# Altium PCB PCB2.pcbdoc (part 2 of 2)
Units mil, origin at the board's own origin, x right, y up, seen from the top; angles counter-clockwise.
Board outline 4625.8 x 3614.6 mil, 4 copper layers (Top Layer, Inner1, Inner2, Bottom Layer); 121 components, 127 nets, 523 pads, 246 vias.
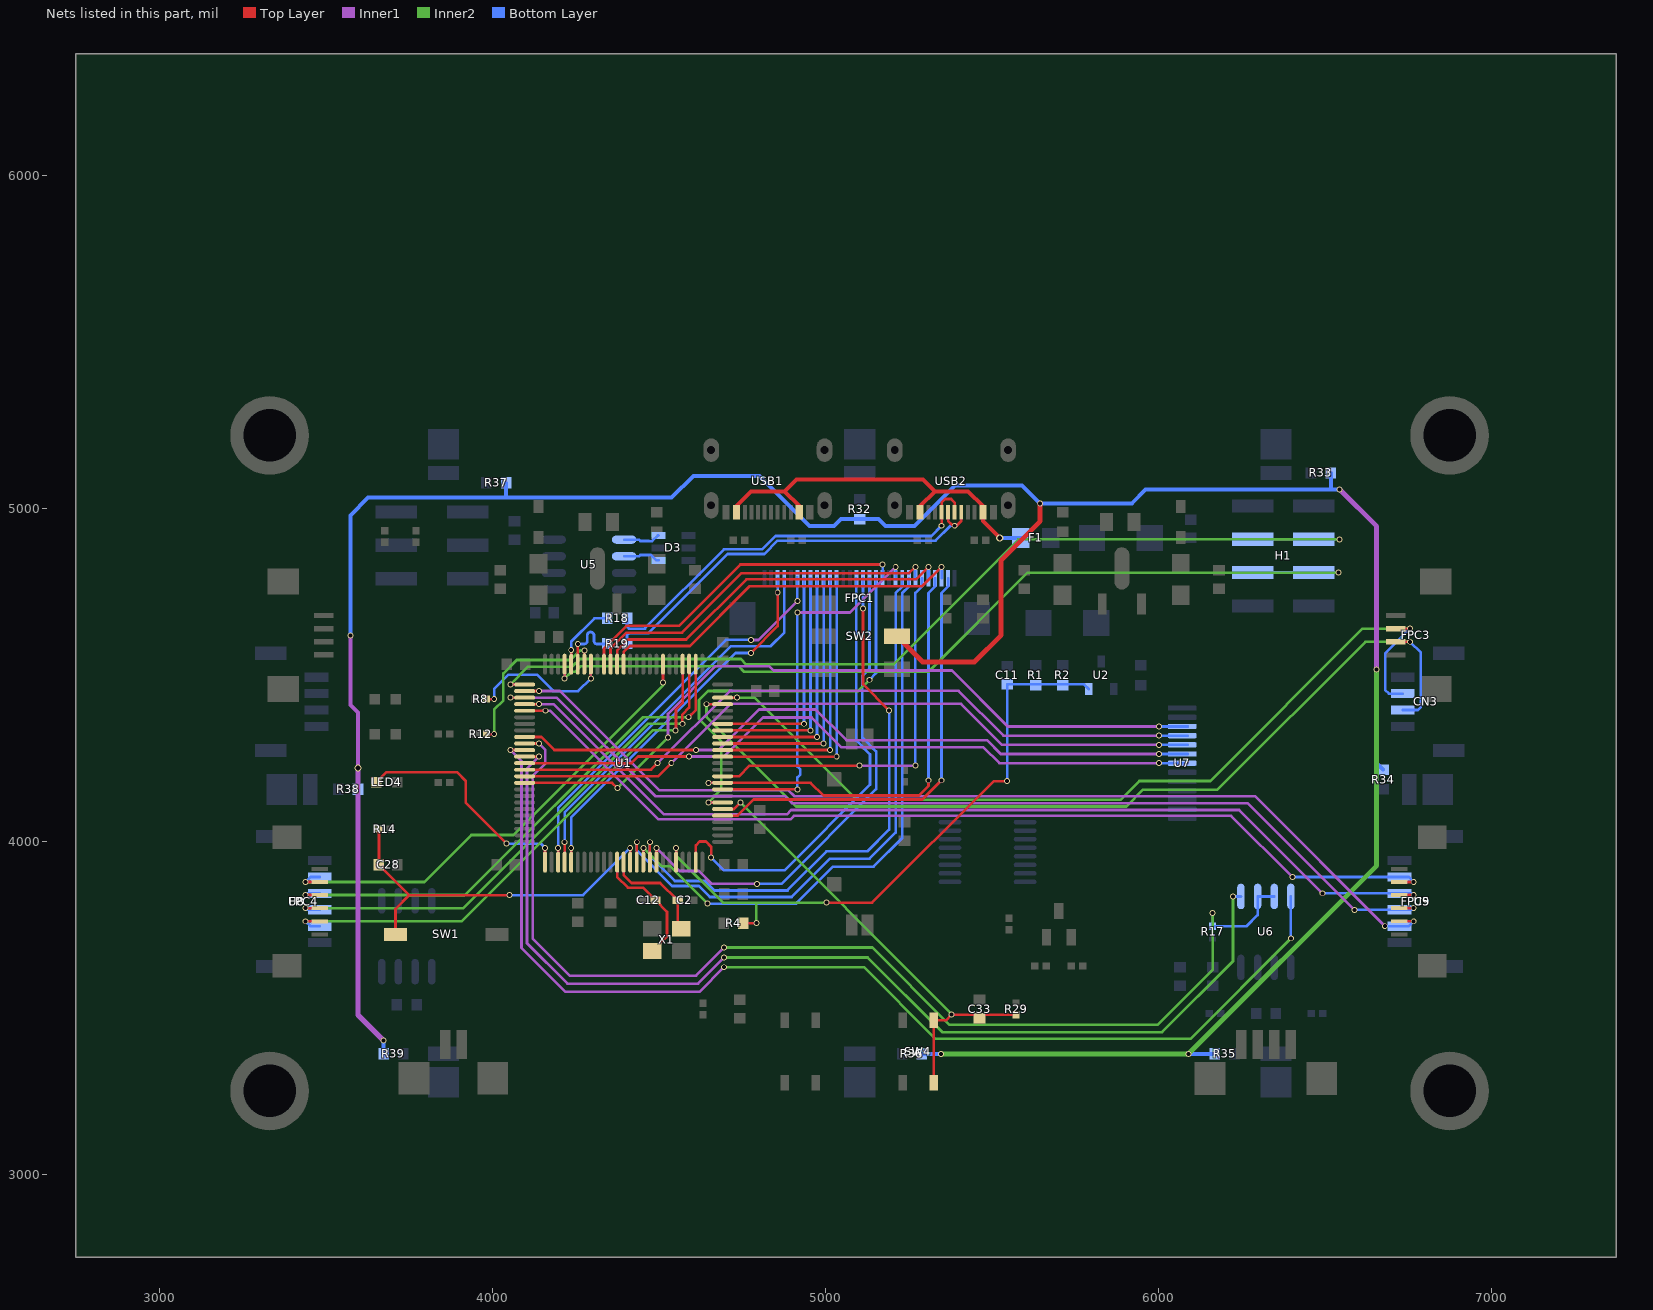
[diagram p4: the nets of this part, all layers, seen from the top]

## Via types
v1: diameter 17.7, hole 12, Top Layer to Bottom Layer, 177 vias
v2: diameter 22, hole 14, Top Layer to Bottom Layer, 62 vias
v3: diameter 17.7, hole 12.01, Top Layer to Bottom Layer, 6 vias
v4: diameter 24, hole 15, Top Layer to Bottom Layer, 1 vias

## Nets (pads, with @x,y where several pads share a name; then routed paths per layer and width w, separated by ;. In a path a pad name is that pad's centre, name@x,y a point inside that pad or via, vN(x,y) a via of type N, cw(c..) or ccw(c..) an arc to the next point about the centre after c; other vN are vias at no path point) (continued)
M0_SPI2_CS: FPC4.5 U1.57 U8.5 | length 1472.9
  Top Layer w8: v1(3440.17,3877.65) FPC4.5@3483.1,3877.6 ; v1(4513.3,4476.86) U1.57@4513.35,4531.59
  Inner2 w8: v1(3440.17,3877.65) 3796.75,3877.65 3937.7,4018.6 4064,4018.6 4513.3,4467.9 v1(4513.3,4476.86)
  Bottom Layer w8: v1(3440.17,3877.65) 3454.94,3892.42 U8.5@3482.8,3892.42
M0_SPI2_MISO: FPC4.3 U1.53 U8.3 | length 1635.9
  Top Layer w8: v1(3440.17,3798.91) FPC4.3@3483.1,3798.9 ; v1(4571.42,4352.61) 4571.27,4352.76 4571.27,4380.11 4592.09,4400.92 U1.53@4592.09,4531.59
  Inner2 w8: v1(3440.17,3798.91) 3913.91,3798.91 4467.61,4352.61 v1(4571.42,4352.61)
  Bottom Layer w8: v1(3440.17,3798.91) 3445.09,3793.99 U8.3@3482.8,3793.99
M0_SPI2_MOSI: FPC4.2 U1.54 U8.2 | length 1647.4
  Top Layer w8: v1(3440.17,3759.54) FPC4.2@3483.1,3759.5 ; v1(4550.75,4332.93) 4552.57,4334.74 4552.57,4394.87 4572.41,4414.71 U1.54@4572.41,4531.59
  Inner2 w8: v1(3440.17,3759.54) 3908.84,3759.54 4482.23,4332.93 v1(4550.75,4332.93)
  Bottom Layer w8: v1(3440.17,3759.54) 3454.93,3744.78 U8.2@3482.8,3744.78
M0_SPI2_SCK: FPC4.4 U1.52 U8.4 | length 1627
  Top Layer w8: v1(3440.17,3838.28) FPC4.4@3483.1,3838.3 ; v1(4590.12,4372.3) 4611.78,4393.95 U1.52@4611.78,4531.59
  Inner2 w8: v1(3440.17,3838.28) 3918.78,3838.28 4452.8,4372.3 v1(4590.12,4372.3)
  Bottom Layer w8: v1(3440.17,3838.28) 3445.1,3843.21 U8.4@3482.8,3843.21
M0_TIM1_CH1: FPC1.20 U1.40 | length 839
  Top Layer w8: U1.40@4692.48,4273.72 v1(5015.31,4273.72)
  Bottom Layer w8: v1(5015.31,4273.72) FPC1.20@5015.31,4789.85
M0_TIM1_CH1N: FPC1.19 U1.39 | length 878.3
  Top Layer w8: U1.39@4692.48,4254.04 v1(5035,4254.04)
  Bottom Layer w8: v1(5035,4254.04) FPC1.19@5035.01,4789.85
M0_TIM1_CH2: FPC1.22 U1.42 | length 760.2
  Top Layer w8: U1.42@4692.48,4313.09 v1(4975.94,4313.09)
  Bottom Layer w8: v1(4975.94,4313.09) FPC1.22@4975.94,4789.85
M0_TIM1_CH2N: FPC1.21 U1.41 | length 799.5
  Top Layer w8: U1.41@4692.48,4293.41 4995.48,4293.41 v1(4995.63,4293.55)
  Bottom Layer w8: v1(4995.63,4293.55) FPC1.21@4995.64,4789.85
M0_TIM1_CH3: FPC1.24 U1.44 | length 681.4
  Top Layer w8: U1.44@4692.48,4352.46 4936.42,4352.46 v1(4936.57,4352.61)
  Bottom Layer w8: v1(4936.57,4352.61) FPC1.24@4936.57,4789.85
M0_TIM1_CH3N: FPC1.23 U1.43 | length 720.8
  Top Layer w8: U1.43@4692.48,4332.78 4956.12,4332.78 v1(4956.27,4332.93)
  Bottom Layer w8: v1(4956.27,4332.93) FPC1.23@4956.27,4789.85
M1_ADC: FPC1.10 U1.34 | length 1148.7
  Top Layer w8: U1.34@4692.48,4155.61 v1(4916.9,4155.61)
  Inner1 w8: v1(4916.9,4686.6) 5074.77,4686.6 v1(5212.18,4824)
  Bottom Layer w8: v1(4916.9,4155.61) 4916.9,4191.59 4925.59,4200.29 4925.59,4215.9 4916.9,4224.6 v1(4916.9,4686.6) ; FPC1.10@5212.17,4790.13 v1(5212.18,4824)
M1_ADC_A: FPC1.9 U1.15 | length 1772.7
  Top Layer w8: U1.15@4434.61,3937.11 v1(4434.61,3997.05)
  Bottom Layer w8: v1(4434.61,3997.05) 4434.61,3971.89 4540.9,3865.6 4620.9,3865.6 4653.9,3832.6 4899.9,3832.6 5014.9,3947.6 5133.8,3947.6 5212,4025.8 5212,4745.31 5231.9,4765.21 FPC1.9@5231.9,4790.08
M1_ADC_C: FPC1.8 U1.16 | length 1760
  Top Layer w8: U1.16@4454.3,3937.11 v1(4454.3,3980.05)
  Inner2 w8: v1(4454.3,3980.05) 4509.75,3924.6 4535.24,3924.6 v1(4647.12,3812.72)
  Bottom Layer w8: v1(4647.12,3812.72) 4913.02,3812.72 5023.9,3923.6 5145.8,3923.6 5231.85,4009.66 5231.85,4745.49 5251.54,4765.17 FPC1.8@5251.54,4790.13
M1_BK_BUTTON: C33.2 R29.2 SW4.1 SW4.2 U1.31 | length 1410.6
  Top Layer w8: U1.31@4692.48,4096.55 4726.13,4096.55 v1(4745.82,4116.24) ; SW4.1@5326.89,3274.5 SW4.2@5326.9,3462.31 5363.41,3462.31 v1(5380.2,3479.1) R29.2@5573.9,3479.06 ; C33.2@5463.9,3468.54 C33.2@5469.16,3473.8
  Inner2 w8: v1(4745.82,4116.24) 5380.2,3481.86 v1(5380.2,3479.1)
M1_BK_OUT: FPC1.25 U1.3 | length 1222.3
  Top Layer w8: U1.3@4198.39,3921.16 v1(4198.39,3980.05)
  Inner1 w8: v1(4777.17,4604.45) 4800.39,4604.45 v1(4916.9,4720.95)
  Bottom Layer w8: v1(4198.39,3980.05) 4198.39,4100.29 4702.7,4604.6 4773.6,4604.6 v1@4773.75,4604.45 ; v1(4916.9,4720.95) FPC1.25@4916.9,4791.86
M1_I2C2_SCL: CN3.3 FPC3.2 U1.47 | length 2825.2
  Top Layer w8: v1(4644.14,4411.37) 4655.87,4411.37 4656.01,4411.52 U1.47@4692.48,4411.52 ; FPC3.2@6713.4,4598.9 v1(6756.34,4598.9)
  Inner2 w8: v1(4644.14,4411.37) 4644.14,4373.18 4912.92,4104.4 5904.7,4104.4 5954.9,4154.6 6177.9,4154.6 6622.2,4598.9 v1(6756.34,4598.9)
  Bottom Layer w8: CN3.3@6735,4393.99 6780.29,4393.99 6788.9,4402.6 6788.9,4566.34 v1(6756.34,4598.9)
M1_I2C2_SDA: CN3.2 FPC3.3 U1.48 | length 2718.6
  Top Layer w8: U1.48@4692.48,4431.2 v1(4735.42,4431.2) ; FPC3.3@6713.4,4638.2 v1(6756.34,4638.2)
  Inner2 w8: v1(4735.42,4431.2) 4787.5,4431.2 5093.9,4124.8 5888.1,4124.8 5943.9,4180.6 6156.9,4180.6 6614.5,4638.2 v1(6756.34,4638.2)
  Bottom Layer w8: CN3.2@6735,4443.21 6693.29,4443.21 6681.9,4454.6 6681.9,4563.76 v1(6756.34,4638.2)
M1_SPI3_CS: FPC5.5 U1.77 U9.5 | length 3011.2
  Top Layer w8: U1.77@4098,4450.89 v1(4140.94,4450.89) ; FPC5.5@6724.7,3759.6 v1(6767.63,3759.55)
  Inner1 w8: v1(4140.94,4450.89) 4203.93,4450.89 4502.22,4152.6 4890,4152.6 4907.5,4135.1 6290.4,4135.1 v1(6680.72,3744.78)
  Bottom Layer w8: v1(6680.72,3744.78) U9.5@6725,3744.78 6752.86,3744.78 v1(6767.63,3759.55)
M1_SPI3_MISO: FPC5.3 U1.79 U9.3 | length 2964.3
  Top Layer w8: U1.79@4098,4411.52 v1(4140.94,4411.52) ; FPC5.3@6724.7,3838.3 v1(6767.63,3838.29)
  Inner1 w8: v1(4140.94,4411.52) 4185.23,4411.52 4515.96,4080.79 4885.09,4080.79 4898,4093.7 6243.65,4093.7 v1(6493.75,3843.6)
  Bottom Layer w8: v1@6493.35,3843.21 v1(6493.75,3843.6) 6727.6,3843.6 U9.3@6728,3843.21 ; U9.3@6725,3843.21 U9.3@6728,3843.21 ; v1(6767.63,3838.29) 6762.71,3843.21 U9.3@6728,3843.21
M1_SPI3_MOSI: FPC5.2 U1.80 U9.2 | length 2934.3
  Top Layer w8: U1.80@4098,4391.83 v1(4161.06,4391.83) ; FPC5.2@6724.7,3877.7 v1(6767.63,3877.66)
  Inner1 w8: v1(4161.06,4391.83) 4173.42,4391.83 4499.46,4065.79 4896.19,4065.79 4906.7,4076.3 6219.64,4076.3 v1(6403.35,3892.59)
  Bottom Layer w8: v1(6403.35,3892.59) 6403.52,3892.42 U9.2@6725,3892.42 6752.87,3892.42 v1(6767.63,3877.66)
M1_SPI3_SCK: FPC5.4 U1.78 U9.4 | length 3064.4
  Top Layer w8: v1(4055.05,4431.2) U1.78@4098,4431.2 ; FPC5.4@6724.7,3798.9 v1(6767.63,3798.92)
  Inner1 w8: v1(4055.05,4431.2) 4194.09,4431.2 4490.07,4135.22 4879.38,4135.22 4900.1,4114.5 6268.8,4114.5 v1(6589.3,3793.99)
  Bottom Layer w8: v1(6589.3,3793.99) U9.4@6725,3793.99 6762.7,3793.99 v1(6767.63,3798.92)
M1_TIM8_CH1: FPC1.3 U1.63 | length 1146.8
  Top Layer w8: U1.63@4395.24,4515.64 4395.24,4567.6 4413.94,4586.3 4594.2,4586.3 4773.5,4765.6 5291.56,4765.6 v1(5349.96,4824)
  Bottom Layer w8: FPC1.3@5349.96,4790.13 v1(5349.96,4824)
M1_TIM8_CH1N: FPC1.2 U1.30 | length 1316.7
  Top Layer w8: U1.30@4692.48,4076.87 4737.17,4076.87 4785.34,4125.04 5291.9,4125.04 v1(5349.9,4183.04)
  Bottom Layer w8: v1(5349.9,4183.04) 5349.9,4745.42 5369.65,4765.17 FPC1.2@5369.65,4790.13
M1_TIM8_CH2: FPC1.5 U1.64 | length 1130.2
  Top Layer w8: U1.64@4375.56,4515.64 4375.56,4572.92 4408.54,4605.9 4583,4605.9 4763.7,4786.6 5273.19,4786.6 v1(5310.59,4824)
  Bottom Layer w8: FPC1.5@5310.59,4790.13 v1(5310.59,4824)
M1_TIM8_CH2N: FPC1.4 U1.35 | length 1321.3
  Top Layer w8: v1(4649.53,4175.29) U1.35@4692.48,4175.29 4956.91,4175.29 4995.16,4137.04 5281.99,4137.04 5310.7,4165.75 v1@5310.7,4182.94
  Bottom Layer w8: v1(5310.7,4183.04) 5310.7,4745.59 5330.28,4765.17 FPC1.4@5330.28,4790.13
M1_TIM8_CH3: FPC1.7 U1.65 | length 1113.7
  Top Layer w8: U1.65@4355.87,4515.64 4355.87,4578.23 4403.84,4626.2 4570.6,4626.2 4749.55,4805.15 5252.37,4805.15 v1(5271.22,4824)
  Bottom Layer w8: FPC1.7@5271.22,4790.13 v1(5271.22,4824)
M1_TIM8_CH3N: FPC1.6 U1.36 | length 1163.3
  Top Layer w8: U1.36@4692.48,4194.98 4741.17,4194.98 4773.14,4226.94 v1(5103.9,4226.94)
  Inner1 w8: v1(5103.9,4226.94) v1(5271.23,4226.9)
  Bottom Layer w8: v1(5271.23,4226.9) 5271.23,4745.49 5290.91,4765.17 FPC1.6@5290.91,4790.13
MOTOR_EN1: FPC1.27 U1.4 | length 1196
  Top Layer w8: U1.4@4218.07,3937.11 v1(4218.07,3997.05)
  Bottom Layer w8: v1(4218.07,3997.05) 4218.07,4086.37 4717.3,4585.6 4836.9,4585.6 4877.52,4626.23 FPC1.27@4877.52,4789.85
MOTOR_EN2: FPC1.28 U1.5 | length 1152.2
  Top Layer w8: U1.5@4237.76,3921.16 v1(4237.76,3980.05) ; v1(4777.17,4565.29) 4857.84,4645.95 v1(4857.84,4746.51)
  Bottom Layer w8: v1(4237.76,3980.05) 4237.76,4071.46 4731.59,4565.29 v1(4777.17,4565.29) ; v1(4857.84,4746.51) FPC1.28@4857.84,4789.85
NRST: C28.2 R14.1 SW1.2 U1.14 | length 1136.2
  Top Layer w8: R14.1@3660.3,4036.44 C28.2@3660.34,3929.05 3751.31,3838.08 ; SW1.2@3710.34,3720.2 3710.34,3797.05 3751.38,3838.08 v1(4052.32,3838.08) ; U1.14@4414.93,3937.11 v1(4414.93,3980.05)
  Bottom Layer w8: v1(4052.32,3838.08) 4272.96,3838.08 v1(4414.93,3980.05)
OSC_IN: C12.1 U1.12 X1.1 | length 357.8
  Top Layer w8: U1.12@4375.56,3921.16 4375.56,3892.94 4407.96,3860.54 4453.01,3860.54 C12.1@4490.76,3822.79 4525.5,3788.05 4525.5,3714.08 X1.1@4481.49,3670.07
OSC_OUT: C2.1 U1.13 X1.3 | length 306.8
  Top Layer w8: U1.13@4395.24,3921.16 4395.24,3898.26 4418.96,3874.54 4504.69,3874.54 4556.44,3822.79 C2.1@4557.84,3822.79 4557.84,3747.27 X1.3@4568.11,3737
OTG_D+: R18.1 USB2.6 USB2.8 | length 1248.7
  Top Layer w8: USB2.8@5349.97,4987.3 5349.97,5016.81 5360.8,5027.65 5378.52,5027.65 5389.34,5016.83 USB2.6@5389.34,4987.3 ; v1(5350,4947.3) USB2.8@5349.97,4987.3
  Bottom Layer w8: R18.1@4405.4,4669.1 4405.4,4644.01 4411.06,4638.35 4457.81,4638.35 ; 4459.15,4638.35 4457.81,4638.35 ; v1(5350,4947.3) 5319.28,4916.58 4851.1,4916.58 4811.11,4876.6 4696.06,4876.6 4457.81,4638.35
OTG_D-: R19.1 USB2.5 USB2.7 | length 1248.9
  Top Layer w8: USB2.7@5369.65,4987.3 5369.65,4961.75 5384.1,4947.3 v1(5389.34,4947.3) 5394.6,4947.3 5409.02,4961.72 USB2.5@5409.02,4987.3
  Bottom Layer w8: R19.1@4405.4,4593.6 4405.4,4618.69 4411.06,4624.35 4468.65,4624.35 ; 4469.99,4624.35 4468.65,4624.35 ; v1(5389.34,4947.3) 5376.66,4947.3 5331.94,4902.58 4857.88,4902.58 4817.9,4862.6 4706.9,4862.6 4468.65,4624.35
PA1: FPC1.16 U1.24 | length 1376.7
  Top Layer w8: U1.24@4611.78,3937.11 4611.78,3987.03 4623.65,3998.9 4642.4,3998.9 4657.9,3983.4 v1(4657.9,3950.7)
  Bottom Layer w8: v1(4657.9,3950.7) 4696,3912.6 4878,3912.6 5135.1,4169.7 5135.1,4260.7 5094.06,4301.74 FPC1.16@5094.06,4789.85
PA7: FPC1.13 U1.32 | length 1244.1
  Top Layer w8: v1(4649.53,4116.24) U1.32@4692.48,4116.24
  Inner2 w8: v1(4649.53,4116.24) 4687.9,4154.6 4687.9,4300.6 4621.7,4366.8 4621.7,4423.4 4649.2,4450.9 5099.58,4450.9 v1(5133.38,4484.7)
  Bottom Layer w8: v1(5133.38,4484.7) 5153.11,4504.43 FPC1.13@5153.11,4790.13
PA9: R8.2 U1.68 | length 440.6
  Top Layer w8: R8.2@3983.28,4426.6 v1(4006.56,4426.6) ; v1(4296.81,4488.64) U1.68@4296.81,4531.59
  Bottom Layer w8: v1(4006.56,4426.6) 4006.56,4456.54 4049.96,4499.94 4135.09,4499.94 4184.44,4450.6 4258.76,4450.6 v1(4296.81,4488.64)
PA10: R12.2 U1.69 | length 529.3
  Top Layer w8: R12.2@3983.28,4321.71 v1(4006.56,4321.71) ; U1.69@4277.13,4531.59 v1(4277.13,4572.53)
  Inner2 w8: v1(4006.56,4321.71) 4006.56,4395.26 4033.9,4422.6 4033.9,4503.65 4074.2,4543.96 4236.06,4543.96 4264.63,4572.53 v1(4277.13,4572.53)
PA11: R19.2 U1.70 | length 204.7
  Top Layer w8: U1.70@4257.44,4531.59 v1(4257.44,4592)
  Bottom Layer w8: v1(4257.44,4592) 4276.17,4592 ccw(c4276.17,4602) 4286.17,4602 4286.17,4618.05 cw(c4296.17,4618.05) 4306.17,4618.05 4306.17,4602 ccw(c4316.17,4602) 4316.17,4592 4344.47,4592 R19.2@4346.08,4593.6
PA12: R18.2 U1.71 | length 204.8
  Top Layer w8: U1.71@4237.76,4531.59 v1(4237.76,4574.53)
  Bottom Layer w8: v1(4237.76,4574.53) 4237.76,4598.97 4307.88,4669.1 R18.2@4346.08,4669.1
PA13: H1.5 H1.6 U1.72 | length 2758.7
  Top Layer w8: v1(4218.07,4488.64) U1.72@4218.07,4531.59
  Inner2 w8: v1(4218.07,4488.64) 4238.32,4508.9 4250.85,4508.9 4267.79,4525.84 4740.33,4525.84 4757.28,4508.9 5310,4508.9 5607.7,4806.6 v1(6541.31,4806.6)
  Bottom Layer w8: H1.5@6284.37,4806.8 H1.6@6467.83,4806.8 ; H1.6@6478.01,4806.6 v1(6541.31,4806.6)
PA14: H1.3 H1.4 U1.76 | length 2973.9
  Top Layer w8: v1(4055.06,4470.57) U1.76@4098,4470.57
  Inner2 w8: v1(4055.06,4470.57) 4108.43,4523.94 4240.84,4523.94 4264.04,4547.14 4747.36,4547.14 4763.3,4531.2 5205.5,4531.2 5580.9,4906.6 v1(6545.4,4906.6)
  Bottom Layer w8: H1.3@6284.37,4906.8 H1.4@6467.83,4906.8 ; H1.4@6482.1,4906.6 v1(6545.4,4906.6)
PB3: U1.89 U7.4 | length 2145.1
  Top Layer w8: U1.89@4098,4214.67 4477.11,4214.67 v1(4496.94,4234.5)
  Inner1 w8: v1(4496.94,4234.5) 4714.05,4451.6 5401.26,4451.6 5535.83,4317.03 v1(6002.65,4317.03)
  Bottom Layer w8: v1(6002.65,4317.03) U7.4@6089.18,4317.03
PB4: U1.90 U7.5 | length 2132.1
  Top Layer w8: U1.90@4098,4194.98 4498.76,4194.98 v1(4538.28,4234.5)
  Inner1 w8: v1(4538.28,4234.5) 4716.13,4412.35 5408.03,4412.35 5530.91,4289.47 v1(6002.65,4289.47)
  Bottom Layer w8: v1(6002.65,4289.47) U7.5@6089.18,4289.47
PB5: U1.91 U7.3 | length 2266.6
  Top Layer w8: U1.91@4098,4175.29 4360.84,4175.29 v1(4376.78,4159.34)
  Inner1 w8: v1(4528.44,4311.27) 4528.44,4382.57 4671.71,4525.85 4832.04,4525.85 4845.39,4512.5 5380.71,4512.5 5548.63,4344.58 v1(6002.65,4344.58)
  Inner2 w8: v1(4376.78,4159.34) 4528.44,4311 v1(4528.44,4311.27)
  Bottom Layer w8: v1(6002.65,4344.58) U7.3@6089.18,4344.58
PC2: FPC1.15 U1.17 | length 1725.9
  Top Layer w8: U1.17@4473.98,3937.11 v1(4473.98,3997.05) ; v1(5113.73,4698.26) 5113.73,4471.77 v1(5192.5,4393)
  Bottom Layer w8: v1(4473.98,3997.05) 4473.98,3955.52 4548.9,3880.6 4639.7,3880.6 4668.35,3851.95 4887.85,3851.95 ; 4887.85,3852.95 5004.5,3969.6 5126.7,3969.6 5192.5,4035.4 v1(5192.5,4393) ; v1@5113.73,4698.22 FPC1.15@5113.74,4790.13
PC3: FPC1.14 U1.18 | length 1525.4
  Top Layer w8: U1.18@4493.67,3937.11 v1(4493.67,3980.05)
  Inner1 w8: v1(4493.67,3980.05) 4563.12,3910.6 4621,3910.6 4659.8,3871.8 v1(4795.1,3871.8)
  Bottom Layer w8: v1(4795.1,3871.8) 4868.8,3871.8 5153.6,4156.6 5153.6,4269.3 5111.9,4311 5111.9,4496.6 5133.43,4518.13 FPC1.14@5133.43,4790.13
PC9: FPC1.12 U1.66 | length 1028.9
  Top Layer w8: U1.66@4336.18,4531.59 4336.18,4578.94 4403.94,4646.7 4561.4,4646.7 4745.43,4830.73 v1(5172.8,4830.73)
  Bottom Layer w8: FPC1.12@5172.8,4790.13 v1(5172.8,4830.73)
PD3: U1.84 U7.6 | length 2113.2
  Top Layer w8: U1.84@4098,4313.09 4147.92,4313.09 4187.14,4273.87 v1(4612.1,4273.87)
  Inner1 w8: v1(4612.1,4273.87) 4680.57,4273.87 4802.3,4395.6 4971.5,4395.6 5063.7,4303.4 5486.1,4303.4 5527.59,4261.91 v1(6002.65,4261.91)
  Bottom Layer w8: v1(6002.65,4261.91) U7.6@6089.18,4261.91
PD4: R17.2 U1.85 U6.2 U6.3 | length 3404.4
  Top Layer w8: U1.85@4098,4293.41 v1(4140.94,4293.41)
  Inner1 w8: v1(4140.94,4293.41) 4159.9,4274.45 4159.9,4233.6 4122.09,4195.79 4122.09,3707.41 4233.31,3596.19 4612.49,3596.19 v1(4696.9,3680.6)
  Inner2 w8: v1(4696.9,3680.6) 5141.9,3680.6 5373.9,3448.6 5998.9,3448.6 6163.9,3613.6 v1(6163.9,3784.18)
  Bottom Layer w8: v1(6163.9,3784.18) R17.2@6163.9,3744.64 6264.94,3744.64 6298.9,3778.6 U6.2@6298.9,3834.1 U6.3@6348.9,3834.1
PD5: U1.86 U6.4 | length 3385.8
  Top Layer w8: v1(4055.06,4273.72) U1.86@4098,4273.72
  Inner1 w8: v1(4055.06,4273.72) 4088.46,4240.31 4088.46,3680.04 4220.6,3547.9 4623.2,3547.9 v1(4696.9,3621.6)
  Inner2 w8: v1(4696.9,3621.6) 5116.9,3621.6 5331.9,3406.6 6096.9,3406.6 v1(6398.9,3708.6)
  Bottom Layer w8: v1(6398.9,3708.6) U6.4@6398.9,3834.1
PD6: U1.87 U6.1 | length 3221.2
  Top Layer w8: U1.87@4098,4254.04 v1(4140.94,4254.04)
  Inner1 w8: v1(4140.94,4254.04) 4104.9,4218 4104.9,3693.6 4226.4,3572.1 4618.4,3572.1 v1(4696.9,3650.6)
  Inner2 w8: v1(4696.9,3650.6) 5127.9,3650.6 5351.9,3426.6 6011.9,3426.6 6224.9,3639.6 v1@6224.9,3834.6
  Bottom Layer w8: v1(6224.9,3834.1) U6.1@6248.9,3834.1
PD7: U1.88 U7.7 | length 2104.9
  Top Layer w8: U1.88@4098,4234.35 4418.65,4234.35 4438.48,4254.18 v1(4592.03,4254.18)
  Inner1 w8: v1(4592.03,4254.18) 4696.22,4254.18 4813.64,4371.6 4959.9,4371.6 5049.5,4282 5475.5,4282 5523.15,4234.35 v1(6002.65,4234.35)
  Bottom Layer w8: v1(6002.65,4234.35) U7.7@6089.18,4234.35
TEST_LED: LED4.1 U1.1 | length 711
  Top Layer w8: LED4.1@3651.83,4176.47 3681.97,4206.6 3895.9,4206.6 3920.9,4181.6 3920.9,4115.71 v1(4043.81,3992.8) ; U1.1@4159.02,3921.16 v1(4159.02,3980.05)
  Bottom Layer w8: v1(4043.81,3992.8) 4146.27,3992.8 v1(4159.02,3980.05)
USB+: D3.6 U5.1 | length 111.9
  Bottom Layer w8: U5.1@4396.63,4905.62 4441.34,4905.62 4445.36,4901.6 4470.25,4901.6 4470.78,4901.07 4480.8,4901.07 4497.73,4918 D3.6@4499.66,4918
USB-: D3.4 U5.2 | length 111.9
  Bottom Layer w8: U5.2@4396.63,4855.62 4441.34,4855.62 4445.33,4859.6 4470.25,4859.6 4470.78,4860.13 4476.93,4860.13 4493.86,4843.2 D3.4@4499.66,4843.2
USB_VCC: F1.1 USB1.2 USB1.11 USB2.2 USB2.11 | length 1168.9
  Top Layer w12: USB1.11@4733.81,4987.29 4733.81,5006.23 4778.28,5050.69 4878.33,5050.69 ; USB1.2@4922.79,4987.29 4923.02,4987.52 4923.02,5006.01 4878.33,5050.69 ; USB2.11@5285,4987.3 5285,5006.24 5329.46,5050.7 ; v2(5524.9,4910.6) 5473.98,4961.52 USB2.2@5473.98,4987.3 5474.2,4987.52 5474.2,5006.01 5429.51,5050.7 5329.46,5050.7 ; 4878.33,5050.69 4914.24,5086.6 5293.56,5086.6 5329.46,5050.7
  Bottom Layer w12: v2(5524.9,4910.6) F1.1@5587.42,4910.6
VCC_+3.3V_2: R32.2 R33.2 R34.2 R35.2 R36.2 R37.2 R38.2 R39.2 SW2.2 | length 8991.5
  Top Layer w15: SW2.2@5216.1,4615.1 5292.6,4538.6 5448.9,4538.6 5528.9,4618.6 5528.9,4843.6 5646.11,4960.81 v1(5646.11,5014.6)
  Inner1 w12: v1(3574.9,4617.6) 3574.9,4409.3 3597.5,4386.7 v2(3597.5,4219.98)
  Inner1 w15: v2(3597.5,4219.98) 3597.5,3478.3 v1(3674.2,3401.6) ; v1(6545.4,5056.4) 6656.48,4945.32 v1(6656.48,4515.55)
  Inner2 w15: v1(5348.46,3361.4) 6090.67,3361.4 v1@6091.08,3361.82 ; v1(6091.5,3361.4) 6656.5,3926.4 v1@6656.5,4515.53
  Bottom Layer w12: v1(3574.9,4617.6) 3574.9,4978.6 3627.9,5031.6 4042.15,5031.6 ; R38.2@3597.5,4155.61 v2(3597.5,4219.98) ; R39.2@3674.24,3361.4 v1(3674.2,3401.6) ; R37.2@4042.15,5076.28 4042.15,5031.6 ; R36.2@5290.56,3361.4 v1(5348.46,3361.4) ; v1@6091.5,3362.23 6092.33,3361.4 R35.2@6170.24,3361.4 ; R33.2@6518.56,5105.8 6518.56,5056.4 ; v1(6545.4,5056.4) 6518.56,5056.4 ; v1(6656.48,4515.55) 6656.5,4234.26 R34.2@6675.83,4214.93 ; 4042.15,5031.6 4538.9,5031.6 4604.37,5097.07 4803.43,5097.07 4953.9,4946.6 5026.9,4946.6 5047.24,4966.94 R32.2@5103.9,4966.94 5160.56,4966.94 5180.9,4946.6 5267.9,4946.6 5390.1,5068.8 5591.91,5068.8 v1(5646.11,5014.6) 5921,5014.6 5962.8,5056.4 6518.56,5056.4
VREF: C11.2 R1.2 R2.2 R4.2 U1.21 U2.2 | length 1915.2
  Top Layer w8: U1.21@4552.72,3937.11 v1@4552.72,3983.15 ; R4.2@4754.81,3754.04 v1@4793.85,3754.04 ; v1(5003.9,3815.39) 5141.57,3815.39 5506.72,4180.54 v1(5546.9,4180.54)
  Inner2 w8: v1(4552.72,3980.06) 4552.72,3956.38 4693.71,3815.39 4793.86,3815.39 ; v1(4793.86,3754.03) 4793.86,3815.39 ; v1(5003.9,3815.39) 4793.86,3815.39
  Bottom Layer w8: v1(5546.9,4180.54) C11.2@5546.9,4471.04 5777.91,4471.04 U2.2@5791.89,4457.06
pads on no net: CN1.5 CN1.6 CN2.5 CN2.6 CN3.5 CN3.6 CN4.3 CN4.4 D4.1 D4.2 D5.1 D5.2 FPC1.31 FPC1.32 FPC2.5 FPC2.6 FPC3.5 FPC3.6 FPC4.7 FPC4.8 FPC5.7 FPC5.8 SW2.3 SW2.6 U1.7 U1.8 U1.9 U1.33 U1.38 U1.45 U1.51 U1.55 U1.56 U1.58 U1.59 U1.67 U1.83 U1.93 U1.97 U1.98 U5.4 U7.1 U7.2 U7.9 U8.7 U8.8 U9.7 U9.8 U10.3 U11.5 USB1.3 USB1.9 USB2.3 USB2.9

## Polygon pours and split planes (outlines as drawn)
DGND on Bottom Layer (solid, remove dead copper, pour order 2): 3000,5499 7125.8,5499 7125.8,3000 3000,3000
DGND on Inner2 (solid, remove dead copper): 3000,5499 7125.8,5499 7125.8,3000 3000,3000
DGND on Inner1 (solid, remove dead copper): 3000,5499 7125.8,5499 7125.8,3000 3000,3000
DGND on Top Layer (solid, remove dead copper, pour order 0): 3000,5499 7125.8,5499 7125.8,3000 3000,3000

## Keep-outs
Top Layer:
  region: 4444.93,3769.63 4604.67,3769.63 4604.67,3637.46 4444.93,3637.46
Inner1:
  region: 4444.93,3769.63 4604.67,3769.63 4604.67,3637.46 4444.93,3637.46
Inner2:
  region: 4444.93,3769.63 4604.67,3769.63 4604.67,3637.46 4444.93,3637.46
Bottom Layer:
  region: 4444.93,3769.63 4604.67,3769.63 4604.67,3637.46 4444.93,3637.46
Board Outline Layer:
  lines w10: 3207.24,3515.92 ccw(c3241.53,3483.55) 3194.46,3486.32 3194.46,3250.1 ccw(c3332.25,3250.1) 3332.25,3112.3 3568.47,3112.3 ccw(c3565.7,3159.38) 3598.08,3125.09 3634.27,3161.29 ; 3207.25,3515.93 3243.44,3552.12 ; 3243.45,3552.13 ccw(c3209.16,3584.5) 3256.23,3581.73 3256.23,4886.96 ccw(c3209.16,4884.2) 3243.45,4916.57 ; 3243.44,4916.58 3207.25,4952.77 cw(c3241.53,4985.15) 3194.46,4982.38 3194.46,5218.6 cw(c3332.25,5218.6) 3332.25,5356.39 3568.47,5356.39 cw(c3565.7,5309.32) 3598.08,5343.61 3634.27,5307.41 ; 3634.28,3161.29 cw(c3666.65,3127) 3663.89,3174.08 6543.92,3174.08 cw(c6541.15,3127) 6573.53,3161.29 6609.72,3125.1 ; 3634.28,5307.4 ccw(c3666.65,5341.69) 3663.88,5294.62 6543.9,5294.62 ccw(c6541.15,5341.69) 6573.53,5307.4 6609.72,5343.6 ; 6609.73,3125.09 ccw(c6642.1,3159.38) 6639.34,3112.3 6875.56,3112.3 ccw(c6875.56,3250.1) 7013.35,3250.1 7013.35,3486.32 ccw(c6966.27,3483.55) 7000.56,3515.92 ; 6609.73,5343.61 cw(c6642.1,5309.32) 6639.34,5356.39 6875.56,5356.39 cw(c6875.56,5218.6) 7013.35,5218.6 7013.35,4982.38 cw(c6966.27,4985.15) 7000.56,4952.78 ; 6964.37,3552.12 7000.56,3515.93 ; 6964.36,3552.13 cw(c6998.65,3584.5) 6951.57,3581.73 6951.57,4886.97 cw(c6998.65,4884.2) 6964.36,4916.57 ; 6964.37,4916.58 7000.56,4952.77

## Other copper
Top Layer:
  drawing of 323 lines, arcs and shapes, not listed
Inner1:
  region net PB5: 5990.6,4340.58 5990.6,4348.58 5992.2,4348.81 5993.89,4349.41 5995.48,4350.25 5996.8,4351.22 5996.8,4337.95 5995.48,4338.92 5993.89,4339.76 5992.2,4340.36
  region net PB3: 5990.6,4313.03 5990.6,4321.03 5992.2,4321.25 5993.89,4321.85 5995.48,4322.69 5996.8,4323.66 5996.8,4310.39 5995.48,4311.36 5993.89,4312.2 5992.2,4312.8
  region net PB4: 5990.6,4285.47 5990.6,4293.47 5992.2,4293.69 5993.89,4294.29 5995.48,4295.14 5996.8,4296.1 5996.8,4282.83 5995.48,4283.8 5993.89,4284.64 5992.2,4285.24
  region net PD7: 5990.6,4230.35 5990.6,4238.35 5992.2,4238.57 5993.89,4239.17 5995.48,4240.02 5996.8,4240.99 5996.8,4227.71 5995.48,4228.68 5993.89,4229.52 5992.2,4230.12
  region net PD3: 5990.6,4257.91 5990.6,4265.91 5992.2,4266.13 5993.89,4266.73 5995.48,4267.58 5996.8,4268.54 5996.8,4255.27 5995.48,4256.24 5993.89,4257.08 5992.2,4257.68
  region net PD6: 4135.25,4242.69 4129.59,4248.35 4130.56,4249.64 4131.33,4251.25 4131.86,4252.98 4132.11,4254.59 4141.5,4245.21 4139.88,4244.96 4138.16,4244.43 4136.54,4243.66
  region net PD5: 4066.4,4268.03 4060.75,4262.37 4059.46,4263.34 4057.84,4264.11 4056.12,4264.64 4054.5,4264.89 4063.89,4274.27 4064.14,4272.66 4064.66,4270.93 4065.43,4269.32
  region net PD4: 4152.29,4287.72 4146.63,4282.06 4145.34,4283.03 4143.73,4283.8 4142.01,4284.33 4140.39,4284.58 4149.77,4293.96 4150.02,4292.35 4150.55,4290.62 4151.32,4289.01
  region net M1_SPI3_SCK: 4067.1,4435.2 4067.1,4427.2 4065.5,4426.97 4063.82,4426.37 4062.23,4425.53 4060.91,4424.56 4060.91,4437.84 4062.23,4436.87 4063.82,4436.02 4065.5,4435.42
  region net BOOT1: 4637.49,4210.67 4637.49,4218.67 4639.09,4218.89 4640.77,4219.49 4642.36,4220.34 4643.68,4221.31 4643.68,4208.03 4642.36,4209 4640.77,4209.84 4639.09,4210.44
  region net +5V: 5943.7,4659.16 5957.84,4673.3 5959.77,4671.49 5961.7,4669.88 5965.28,4667.27 5968.04,4665.49 5969.44,4664.53 5952.46,4647.56 5951.51,4648.96 5949.72,4651.72 5947.11,4655.3 5945.51,4657.23
  region net +5V: 4474.75,4890.6 4474.75,4870.6 4470.05,4870.44 4466.05,4870.1 4461.55,4869.6 4461.55,4891.6 4466.05,4891.1 4470.05,4890.76
  region net +5V: 3762.9,3745.68 3774.9,3745.68 3775.01,3743.66 3775.39,3741.58 3776.08,3739.63 3777.15,3737.98 3760.65,3737.98 3761.72,3739.63 3762.41,3741.58 3762.79,3743.66
  region net PC3: 4505.02,3974.36 4499.36,3968.7 4498.07,3969.67 4496.45,3970.44 4494.73,3970.97 4493.11,3971.22 4502.5,3980.61 4502.75,3978.99 4503.28,3977.27 4504.05,3975.65
  region net PC3: 4783.05,3867.8 4783.05,3875.8 4784.65,3876.03 4786.34,3876.62 4787.93,3877.47 4789.25,3878.44 4789.25,3865.16 4787.93,3866.13 4786.34,3866.98 4784.65,3867.57
  region net M0_ADC_C: 4704.53,3984.8 4704.53,3976.8 4702.93,3976.58 4701.24,3975.98 4699.65,3975.14 4698.33,3974.17 4698.33,3987.44 4699.65,3986.47 4701.24,3985.63 4702.93,3985.03
  region net M1_TIM8_CH3N: 5259.14,4222.94 5259.21,4230.94 5260.81,4231.17 5262.49,4231.76 5264.08,4232.6 5265.4,4233.57 5265.34,4220.29 5264.02,4221.27 5262.43,4222.12 5260.74,4222.72
  region net M1_TIM8_CH3N: 5115.95,4230.94 5115.95,4222.94 5114.35,4222.72 5112.66,4222.12 5111.07,4221.28 5109.75,4220.31 5109.75,4233.58 5111.07,4232.61 5112.66,4231.77 5114.35,4231.17
  region net M1_SPI3_SCK: 6577.95,3799.68 6583.61,3805.34 6584.9,3804.37 6586.52,3803.6 6588.24,3803.07 6589.86,3802.83 6580.47,3793.44 6580.22,3795.06 6579.69,3796.78 6578.92,3798.39
  region net M1_SPI3_MOSI: 6392,3898.28 6397.66,3903.93 6398.95,3902.96 6400.57,3902.2 6402.29,3901.67 6403.91,3901.42 6394.52,3892.03 6394.27,3893.65 6393.74,3895.37 6392.98,3896.99
  region net M0_BK_BUTTON: 4820.9,3938.75 4812.9,3938.75 4812.67,3940.35 4812.08,3942.04 4811.23,3943.63 4810.26,3944.95 4823.54,3944.95 4822.57,3943.63 4821.72,3942.04 4821.13,3940.35
  region net M1_BK_OUT: 4789.22,4608.45 4789.22,4600.45 4787.62,4600.22 4785.94,4599.63 4784.35,4598.78 4783.03,4597.81 4783.03,4611.09 4784.35,4610.12 4785.94,4609.27 4787.62,4608.68
  region net M0_BK_OUT: 4829.71,4740.81 4824.05,4735.15 4822.76,4736.12 4821.15,4736.89 4819.43,4737.42 4817.81,4737.67 4827.2,4747.05 4827.44,4745.44 4827.97,4743.71 4828.74,4742.1
  region net M0_BK_OUT: 4891.51,4735.16 4885.86,4740.82 4886.83,4742.11 4887.6,4743.72 4888.12,4745.45 4888.37,4747.07 4897.76,4737.68 4896.14,4737.43 4894.42,4736.9 4892.8,4736.13
  region net M1_BK_OUT: 4911.2,4709.6 4905.55,4715.26 4906.52,4716.55 4907.29,4718.16 4907.81,4719.89 4908.06,4721.5 4917.45,4712.12 4915.83,4711.87 4914.11,4711.34 4912.49,4710.57
  region net M1_SPI3_MISO: 6482.4,3849.3 6488.06,3854.95 6489.35,3853.98 6490.96,3853.21 6492.69,3852.68 6494.3,3852.44 6484.92,3843.05 6484.67,3844.67 6484.14,3846.39 6483.37,3848
  region net PD7: 4604.08,4258.18 4604.08,4250.18 4602.48,4249.96 4600.8,4249.36 4599.2,4248.51 4597.88,4247.54 4597.88,4260.82 4599.2,4259.85 4600.8,4259.01 4602.48,4258.41
  region net PB3: 4502.63,4245.84 4508.29,4240.19 4507.32,4238.9 4506.55,4237.28 4506.02,4235.56 4505.77,4233.94 4496.39,4243.33 4498,4243.58 4499.73,4244.1 4501.34,4244.87
  region net PB4: 4543.97,4245.84 4549.63,4240.19 4548.66,4238.9 4547.89,4237.28 4547.36,4235.56 4547.11,4233.94 4537.73,4243.33 4539.34,4243.58 4541.07,4244.1 4542.68,4244.87
  region net PB5: 4524.44,4323.32 4532.44,4323.32 4532.67,4321.72 4533.26,4320.04 4534.11,4318.44 4535.08,4317.13 4521.8,4317.13 4522.77,4318.44 4523.61,4320.04 4524.21,4321.72
  region net M0_BK_BUTTON: 4812.9,3524.97 4820.9,3525.12 4821.13,3523.52 4821.73,3521.83 4822.59,3520.24 4823.57,3518.93 4810.3,3518.78 4811.25,3520.1 4812.09,3521.69 4812.68,3523.38
  region net BACKLIGHT: 4734.85,3788.54 4734.85,3796.54 4736.45,3796.77 4738.14,3797.37 4739.73,3798.21 4741.05,3799.18 4741.05,3785.91 4739.73,3786.88 4738.14,3787.72 4736.45,3788.32
  region net LEDC: 3952.9,4171.55 3944.9,4171.55 3944.67,4173.15 3944.08,4174.84 3943.23,4176.43 3942.26,4177.75 3955.54,4177.75 3954.57,4176.43 3953.72,4174.84 3953.13,4173.15
  region net LEDB: 3981.24,4171.55 3973.24,4171.55 3973.01,4173.15 3972.41,4174.84 3971.57,4176.43 3970.6,4177.75 3983.88,4177.75 3982.91,4176.43 3982.06,4174.84 3981.47,4173.15
  region net LEDA: 4007.24,4171.55 3999.24,4171.55 3999.01,4173.15 3998.41,4174.84 3997.57,4176.43 3996.6,4177.75 4009.88,4177.75 4008.91,4176.43 4008.06,4174.84 4007.47,4173.15
  region net LEDC: 5680.21,3994.25 5674.55,3999.91 5675.52,4001.2 5676.29,4002.81 5676.82,4004.54 5677.07,4006.15 5686.45,3996.77 5684.84,3996.52 5683.11,3995.99 5681.5,3995.22
  region net LEDB: 5661.21,4020.23 5655.55,4025.89 5656.52,4027.18 5657.29,4028.79 5657.82,4030.52 5658.07,4032.13 5667.45,4022.75 5665.84,4022.5 5664.11,4021.97 5662.5,4021.2
  region net LEDA: 5643.21,4045.25 5637.55,4050.91 5638.52,4052.2 5639.29,4053.81 5639.82,4055.54 5640.07,4057.15 5649.45,4047.77 5647.84,4047.52 5646.11,4046.99 5644.5,4046.22
  region net $1N103001: 5909.52,3652.25 5909.52,3637.25 5905.76,3637.04 5902.59,3636.57 5898.9,3635.9 5898.9,3653.6 5902.59,3652.93 5905.76,3652.46
  region net VCC_+3.3V_2: 3580.9,4605.55 3568.9,4605.55 3569.05,4607.39 3569.26,4608.91 3569.13,4610.3 3568.81,4611 3568.26,4611.75 3581.54,4611.75 3580.99,4611 3580.67,4610.3 3580.54,4608.91 3580.75,4607.39
  region net VCC_+3.3V_2: 3661.39,3403.81 3671.99,3414.41 3674.8,3411.9 3677.37,3409.99 3680.46,3407.86 3667.94,3395.34 3665.81,3398.43 3663.9,3401
  region net $1N102744: 5665.4,5115.1 5665.4,5100.1 5661.64,5099.89 5658.47,5099.43 5654.78,5098.75 5654.78,5116.45 5658.47,5115.77 5661.64,5115.31
  region net $1N102744: 6024.52,3620.1 6024.52,3605.1 6020.76,3604.89 6017.59,3604.43 6013.9,3603.75 6013.9,3621.45 6017.59,3620.78 6020.76,3620.31
  region net $1N103001: 6558.21,5155.61 6547.61,5145 6544.8,5147.51 6542.23,5149.42 6539.14,5151.56 6551.66,5164.07 6553.79,5160.98 6555.7,5158.42
  region net VCC_+3.3V_2: 6648.98,4526.17 6663.98,4526.17 6664.19,4522.41 6664.65,4519.24 6665.33,4515.55 6647.63,4515.55 6648.3,4519.24 6648.77,4522.41
  region net VCC_+3.3V_2: 6558.21,5054.19 6547.61,5043.59 6544.8,5046.1 6542.23,5048.01 6539.14,5050.14 6551.66,5062.66 6553.79,5059.57 6555.7,5057
  region net +5V: 4084.32,4631.7 4084.32,4643.7 4086.34,4643.81 4088.41,4644.19 4090.37,4644.88 4092.02,4645.95 4092.02,4629.45 4090.37,4630.52 4088.41,4631.21 4086.34,4631.59
  region net M1_SPI3_CS: 6669.37,3750.47 6675.03,3756.13 6676.32,3755.16 6677.93,3754.39 6679.66,3753.86 6681.27,3753.61 6671.89,3744.23 6671.64,3745.84 6671.11,3747.57 6670.34,3749.18
  region net VCC_+3.3V_2: 3605,4205 3590,4205 3590.2,4207.29 3590.47,4209.17 3590.48,4210.04 3590.32,4210.9 3589.93,4211.77 3589.25,4212.7 3605.75,4212.7 3605.06,4211.77 3604.67,4210.9 3604.51,4210.04 3604.52,4209.17 3604.8,4207.29
  region net VCC_+3.3V_2: 3591.5,4234.95 3603.5,4234.95 3603.61,4232.94 3603.98,4230.86 3604.68,4228.91 3605.75,4227.25 3589.25,4227.25 3590.32,4228.91 3591.01,4230.86 3591.39,4232.94
  region net CAN1_TX: 3723.9,4012.65 3731.9,4012.65 3732.13,4011.05 3732.72,4009.36 3733.57,4007.77 3734.54,4006.45 3721.26,4006.45 3722.23,4007.77 3723.08,4009.36 3723.67,4011.05
  region net CAN1_RX: 3755.9,4012.65 3763.9,4012.65 3764.13,4011.05 3764.72,4009.36 3765.57,4007.77 3766.54,4006.45 3753.26,4006.45 3754.23,4007.77 3755.08,4009.36 3755.67,4011.05
  region net CAN1_RX: 4059.05,4360.1 4051.05,4360.1 4050.83,4361.7 4050.23,4363.38 4049.39,4364.98 4048.42,4366.29 4061.69,4366.29 4060.72,4364.98 4059.88,4363.38 4059.28,4361.7
  region net BACKLIGHT: 4152.29,4149.92 4146.63,4144.26 4145.34,4145.23 4143.73,4146 4142.01,4146.53 4140.39,4146.78 4149.77,4156.16 4150.02,4154.55 4150.55,4152.82 4151.32,4151.21
  region net PD4: 4691.21,3669.25 4685.55,3674.91 4686.52,3676.2 4687.29,3677.81 4687.82,3679.54 4688.07,3681.15 4697.45,3671.77 4695.84,3671.52 4694.11,3670.99 4692.5,3670.22
  region net M0_ADC_C: 4903.84,3976.8 4903.84,3984.8 4905.44,3985.03 4907.12,3985.63 4908.71,3986.47 4910.03,3987.44 4910.03,3974.17 4908.71,3975.14 4907.12,3975.98 4905.43,3976.58
  region net M1_ADC: 4928.95,4690.6 4928.95,4682.6 4927.35,4682.37 4925.66,4681.78 4924.07,4680.93 4922.75,4679.96 4922.75,4693.24 4924.07,4692.27 4925.66,4691.42 4927.35,4690.83
  region net M1_ADC: 5206.48,4812.65 5200.83,4818.31 5201.8,4819.6 5202.57,4821.22 5203.09,4822.94 5203.34,4824.56 5212.73,4815.17 5211.11,4814.92 5209.39,4814.39 5207.77,4813.62
  region net +3.3V_2: 5555.7,4803.09 5555.7,4823.09 5560.41,4823.25 5564.4,4823.59 5568.9,4824.09 5568.9,4802.09 5564.4,4802.59 5560.41,4802.93
  region net +3.3V_2: 5476.16,4770 5490.3,4755.86 5487.09,4752.42 5484.51,4749.36 5481.68,4745.82 5466.12,4761.38 5469.66,4764.21 5472.72,4766.79
  region net BOOT1: 3844.59,4936.43 3844.59,4928.43 3842.99,4928.2 3841.31,4927.61 3839.72,4926.76 3838.4,4925.79 3838.4,4939.07 3839.72,4938.1 3841.31,4937.26 3842.99,4936.66
Inner2:
  region net BOOT0: 4043.01,4112.24 4043.01,4120.24 4044.61,4120.46 4046.29,4121.06 4047.88,4121.91 4049.2,4122.88 4049.2,4109.6 4047.88,4110.57 4046.29,4111.41 4044.61,4112.01
  region net BOOT0: 3620.66,4920.31 3612.66,4920.31 3612.43,4921.91 3611.84,4923.6 3610.99,4925.19 3610.02,4926.51 3623.3,4926.51 3622.33,4925.19 3621.48,4923.6 3620.89,4921.91
  region net PA14: 4060.75,4481.92 4066.4,4476.26 4065.43,4474.97 4064.66,4473.35 4064.14,4471.63 4063.89,4470.01 4054.5,4479.4 4056.12,4479.65 4057.84,4480.18 4059.46,4480.95
  region net PA10: 4002.56,4333.75 4010.56,4333.75 4010.78,4332.16 4011.38,4330.47 4012.22,4328.88 4013.19,4327.56 3999.92,4327.56 4000.89,4328.88 4001.73,4330.47 4002.33,4332.16
  region net PA13: 4223.76,4499.99 4229.42,4494.34 4228.45,4493.04 4227.68,4491.43 4227.15,4489.71 4226.9,4488.09 4217.51,4497.48 4219.13,4497.72 4220.85,4498.25 4222.47,4499.02
  region net PA10: 4265.08,4568.53 4265.08,4576.53 4266.68,4576.76 4268.36,4577.36 4269.96,4578.2 4271.27,4579.17 4271.27,4565.89 4269.96,4566.86 4268.36,4567.71 4266.68,4568.3
  region net VREF: 4556.72,3968.01 4548.72,3968.01 4548.49,3969.61 4547.89,3971.29 4547.05,3972.88 4546.08,3974.2 4559.36,3974.2 4558.39,3972.88 4557.54,3971.29 4556.95,3969.61
  region net M1_I2C2_SCL: 4648.14,4399.32 4640.14,4399.32 4639.91,4400.92 4639.31,4402.61 4638.47,4404.2 4637.5,4405.52 4650.77,4405.52 4649.8,4404.2 4648.96,4402.61 4648.36,4400.92
  region net M1_ADC_C: 4465.65,3974.36 4459.99,3968.7 4458.7,3969.67 4457.08,3970.44 4455.36,3970.97 4453.74,3971.22 4463.13,3980.61 4463.38,3978.99 4463.91,3977.27 4464.68,3975.65
  region net M1_BK_BUTTON: 4757.17,4110.55 4751.51,4104.89 4750.22,4105.86 4748.61,4106.63 4746.89,4107.16 4745.27,4107.41 4754.65,4116.79 4754.9,4115.17 4755.43,4113.45 4756.2,4111.84
  region net PA7: 5127.69,4473.35 5122.03,4479.01 5123,4480.3 5123.77,4481.92 5124.3,4483.64 5124.55,4485.26 5133.93,4475.87 5132.32,4475.62 5130.59,4475.09 5128.98,4474.33
  region net +3.3V_2: 5173.39,4366.93 5173.39,4354.93 5171.38,4354.82 5169.3,4354.44 5167.35,4353.75 5165.69,4352.68 5165.69,4369.18 5167.35,4368.11 5169.3,4367.42 5171.38,4367.04
  region net +3.3V_2: 5425.56,4557.26 5413.56,4557.26 5413.45,4559.28 5413.07,4561.36 5412.38,4563.31 5411.31,4564.96 5427.81,4564.96 5426.74,4563.31 5426.05,4561.36 5425.67,4559.28
  region net M1_ADC_C: 4635.77,3818.41 4641.43,3824.07 4642.72,3823.1 4644.33,3822.33 4646.06,3821.8 4647.68,3821.55 4638.29,3812.17 4638.04,3813.78 4637.51,3815.51 4636.74,3817.12
  region net M0_SPI2_SCK: 4578.08,4368.3 4578.08,4376.3 4579.67,4376.52 4581.36,4377.12 4582.95,4377.97 4584.27,4378.94 4584.27,4365.66 4582.95,4366.63 4581.36,4367.47 4579.67,4368.07
  region net M0_SPI2_CS: 4517.3,4467.9 4509.3,4467.9 4509.07,4469.02 4508.48,4469.64 4507.63,4470.17 4506.66,4471.01 4519.94,4471.01 4518.97,4470.17 4518.12,4469.64 4517.53,4469.02
  region net PB5: 4522.99,4299.89 4517.13,4305.34 4518.1,4306.64 4518.86,4308.27 4519.37,4310.01 4519.6,4311.63 4529.19,4302.45 4527.58,4302.18 4525.87,4301.64 4524.27,4300.86
  region net VREF: 4991.85,3811.39 4991.85,3819.39 4993.45,3819.62 4995.14,3820.22 4996.73,3821.06 4998.05,3822.03 4998.05,3808.76 4996.73,3809.73 4995.14,3810.57 4993.45,3811.17
  region net VREF: 4789.86,3766.08 4797.86,3766.08 4798.09,3764.48 4798.68,3762.8 4799.53,3761.21 4800.5,3759.89 4787.22,3759.89 4788.19,3761.21 4789.04,3762.8 4789.63,3764.48
  region net M1_BK_BUTTON: 5369.3,3487.1 5377.03,3490.69 5378.22,3489.72 5379.68,3488.84 5381.23,3488.11 5382.69,3487.59 5371.46,3480.51 5371.45,3482.16 5371.02,3484.01 5370.27,3485.76
  region net LEDC: 4328.89,4486.24 4334.55,4491.89 4335.84,4490.92 4337.45,4490.15 4339.18,4489.62 4340.79,4489.38 4331.41,4479.99 4331.16,4481.61 4330.63,4483.33 4329.86,4484.95
  region net LEDB: 4305.19,4456.39 4305.19,4464.39 4306.79,4464.62 4308.47,4465.22 4310.07,4466.06 4311.38,4467.03 4311.38,4453.76 4310.07,4454.73 4308.47,4455.57 4306.79,4456.17
  region net LEDA: 4286.55,4429.2 4280.89,4434.85 4281.86,4436.14 4282.63,4437.76 4283.16,4439.48 4283.41,4441.1 4292.79,4431.71 4291.18,4431.46 4289.45,4430.94 4287.84,4430.17
  region net LEDC: 3944.9,4195.65 3952.9,4195.65 3953.13,4194.05 3953.72,4192.36 3954.57,4190.77 3955.54,4189.45 3942.26,4189.45 3943.23,4190.77 3944.08,4192.36 3944.67,4194.05
  region net LEDB: 3973.24,4195.65 3981.24,4195.65 3981.47,4194.05 3982.06,4192.36 3982.91,4190.77 3983.88,4189.45 3970.6,4189.45 3971.57,4190.77 3972.41,4192.36 3973.01,4194.05
  region net LEDA: 4008.93,4194.95 4014.59,4189.29 4013.62,4188 4012.85,4186.39 4012.32,4184.66 4012.07,4183.05 4002.68,4192.43 4004.3,4192.68 4006.02,4193.21 4007.64,4193.98
  region net +5V: 5397.18,4178.36 5405.66,4169.88 5404.26,4168.69 5403.04,4167.76 5402.15,4166.68 5401.87,4165.96 5401.73,4165.05 5392.35,4174.43 5393.26,4174.57 5393.98,4174.85 5395.06,4175.74 5395.99,4176.96
  region net +5V: 5476.9,4488.85 5464.9,4488.85 5465.05,4490.69 5465.26,4492.21 5465.13,4493.6 5464.81,4494.3 5464.26,4495.05 5477.54,4495.05 5476.99,4494.3 5476.67,4493.6 5476.54,4492.21 5476.75,4490.69
  region net $1N103341: 5841.28,3673.1 5841.28,3688.1 5845.04,3688.31 5848.21,3688.78 5851.9,3689.45 5851.9,3671.75 5848.21,3672.43 5845.04,3672.89
  region net $1N103341: 5443.71,3978.18 5433.11,3967.58 5430.3,3970.09 5427.73,3972 5424.64,3974.13 5437.16,3986.65 5439.29,3983.56 5441.2,3980.99
  region net $1N103001: 5465.71,4003.39 5455.11,3992.79 5452.3,3995.3 5449.73,3997.21 5446.64,3999.34 5459.16,4011.86 5461.29,4008.77 5463.2,4006.2
  region net $1N103001: 5891.4,3655.37 5906.4,3655.37 5906.61,3651.61 5907.07,3648.44 5907.75,3644.75 5890.05,3644.75 5890.73,3648.44 5891.19,3651.61
  region net $1N102744: 5441.52,4039.08 5441.52,4024.08 5437.76,4023.87 5434.59,4023.41 5430.9,4022.73 5430.9,4040.43 5434.59,4039.76 5437.76,4039.29
  region net VCC_+3.3V_2: 6080.88,3353.9 6080.88,3368.9 6084.64,3369.11 6087.81,3369.57 6091.5,3370.25 6091.5,3352.55 6087.81,3353.22 6084.64,3353.69
  region net VCC_+3.3V_2: 6093.71,3374.21 6104.31,3363.61 6101.8,3360.8 6099.89,3358.23 6097.76,3355.14 6085.24,3367.66 6088.33,3369.79 6090.9,3371.7
  region net $1N102744: 6001.09,3614.81 6011.69,3625.41 6014.5,3622.9 6017.07,3620.99 6020.16,3618.86 6007.64,3606.34 6005.51,3609.43 6003.6,3612
  region net VCC_+3.3V_2: 6664,4504.95 6649,4504.91 6648.79,4508.07 6648.32,4510.22 6647.85,4512.36 6647.63,4515.53 6665.33,4515.57 6665.13,4512.41 6664.67,4510.26 6664.21,4508.12
  region net PB5: 4382.48,4170.69 4388.13,4165.03 4387.16,4163.74 4386.39,4162.13 4385.87,4160.41 4385.62,4158.79 4376.23,4168.18 4377.85,4168.42 4379.57,4168.95 4381.19,4169.72
  region net PA14: 6533.35,4902.6 6533.35,4910.6 6534.95,4910.83 6536.64,4911.42 6538.23,4912.27 6539.55,4913.24 6539.55,4899.96 6538.23,4900.93 6536.64,4901.78 6534.95,4902.37
  region net PA13: 6529.26,4802.6 6529.26,4810.6 6530.86,4810.83 6532.54,4811.42 6534.13,4812.27 6535.45,4813.24 6535.45,4799.96 6534.13,4800.93 6532.54,4801.78 6530.86,4802.37
  region net M1_I2C2_SDA: 6744.29,4634.2 6744.29,4642.2 6745.89,4642.43 6747.58,4643.02 6749.17,4643.87 6750.49,4644.84 6750.49,4631.56 6749.17,4632.53 6747.58,4633.38 6745.89,4633.97
  region net M1_I2C2_SCL: 6744.29,4594.9 6744.29,4602.9 6745.89,4603.13 6747.58,4603.72 6749.17,4604.57 6750.49,4605.54 6750.49,4592.26 6749.17,4593.23 6747.58,4594.08 6745.89,4594.67
  region net M0_SPI2_MOSI: 3452.22,3763.54 3452.22,3755.54 3450.62,3755.31 3448.94,3754.72 3447.34,3753.87 3446.03,3752.9 3446.03,3766.18 3447.34,3765.21 3448.94,3764.36 3450.62,3763.77
  region net M0_SPI2_MISO: 3452.22,3802.91 3452.22,3794.91 3450.62,3794.68 3448.94,3794.09 3447.34,3793.24 3446.03,3792.27 3446.03,3805.55 3447.34,3804.58 3448.94,3803.73 3450.62,3803.14
  region net M0_SPI2_SCK: 3452.22,3842.28 3452.22,3834.28 3450.62,3834.05 3448.94,3833.46 3447.34,3832.61 3446.03,3831.64 3446.03,3844.92 3447.34,3843.95 3448.94,3843.1 3450.62,3842.51
  region net M0_SPI2_CS: 3452.22,3881.65 3452.22,3873.65 3450.62,3873.42 3448.94,3872.83 3447.34,3871.98 3446.03,3871.01 3446.03,3884.29 3447.34,3883.32 3448.94,3882.47 3450.62,3881.88
  region net PD6: 4708.95,3654.6 4708.95,3646.6 4707.35,3646.37 4705.66,3645.78 4704.07,3644.93 4702.75,3643.96 4702.75,3657.24 4704.07,3656.27 4705.66,3655.42 4707.35,3654.83
  region net PD6: 6228.9,3822.05 6220.9,3822.05 6220.67,3823.65 6220.08,3825.34 6219.23,3826.93 6218.26,3828.25 6231.54,3828.25 6230.57,3826.93 6229.72,3825.34 6229.13,3823.65
  region net PD5: 6393.21,3697.25 6387.55,3702.91 6388.52,3704.2 6389.29,3705.81 6389.82,3707.54 6390.07,3709.15 6399.45,3699.77 6397.84,3699.52 6396.11,3698.99 6394.5,3698.22
  region net PD4: 6167.9,3772.13 6159.9,3772.13 6159.67,3773.73 6159.08,3775.42 6158.23,3777.01 6157.26,3778.33 6170.54,3778.33 6169.57,3777.01 6168.73,3775.42 6168.13,3773.73
  region net PD5: 4708.95,3625.6 4708.95,3617.6 4707.35,3617.37 4705.66,3616.78 4704.07,3615.93 4702.75,3614.96 4702.75,3628.24 4704.07,3627.27 4705.66,3626.42 4707.35,3625.83
  region net PD4: 4708.95,3684.6 4708.95,3676.6 4707.35,3676.37 4705.66,3675.78 4704.07,3674.93 4702.75,3673.96 4702.75,3687.24 4704.07,3686.27 4705.66,3685.42 4707.35,3684.83
  region net PA7: 4655.23,4127.59 4660.88,4121.93 4659.91,4120.64 4659.14,4119.02 4658.62,4117.3 4658.37,4115.68 4648.98,4125.07 4650.6,4125.32 4652.32,4125.85 4653.94,4126.62
  region net VCC_+3.3V_2: 5359.08,3368.9 5359.08,3353.9 5355.32,3353.69 5352.15,3353.22 5348.46,3352.55 5348.46,3370.25 5352.15,3369.57 5355.32,3369.11
  region net VREF: 4789.86,3787.39 ccw(c4749.86,3787.39) 4781.86,3811.39 4793.86,3815.39 4805.86,3811.39 ccw(c4837.86,3787.39) 4797.86,3787.39
Bottom Layer:
  drawing of 288 lines, arcs and shapes, not listed

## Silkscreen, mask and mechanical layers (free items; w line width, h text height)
Top Silkscreen Layer:
  drawing of 355 lines, arcs and shapes, not listed
  text "USB1" at 4199.09,5080.19 h80
  text "USB2" at 5805.55,5080.19 h80
  text "link" at 6415.48,5061.65 h50
  text "ST" at 6318.27,5056.71 h50
  text "BOOT" at 3655.49,5009.39 h50
  text "GND" at 6369.57,4969.12 h50
  text "I2C1" at 3319.99,4920.24 h50
  text "I2C2" at 6780.99,4920.24 h50
  text "L" at 3713.55,4911.6 h50
  text "SWCLK" at 6334.67,4883.81 h50
  text "H" at 3710.3,4865.6 h50
  text "SWDIO" at 6342.02,4798.5 h50
  text "B0/B1" at 3651,4787.43 h50
  text "3.3V" at 6360.87,4713.19 h50
  text "SW" at 4817.4,4659.9 h50
  text "3.3" at 3537.38,4655.61 h40
  text "GND" at 6605.48,4655.61 h40
  text "SCL" at 3531.53,4615.91 h40
  text "SDA" at 6604.93,4615.91 h40
  text "ON" at 4791.9,4589.9 h50
  text "SDA" at 3529.93,4576.21 h40
  text "SCL" at 6606.53,4576.21 h40
  text "GND" at 3530.48,4536.51 h40
  text "3.3" at 6612.38,4536.51 h40
  text "OFF" at 4802.4,4533 h50
  text "TX-PA9" at 3598.85,4459.6 h40
  text "JLCJLCJLCJLC" at 5696.9,4389.6 h39.37
  text "RX-PA10" at 3598.85,4247.9 h40
  text "H" at 4937.31,4178.32 h60
  text "SPI2" at 3333,4161.95 h50
  text "SPI3" at 6771.37,4156.95 h50
  text "TEST-PE2" at 3580.8,4103.48 h40
  text "LIGHT" at 4893.4,4001.16 h40
  text "3.3" at 3532.38,3895.1 h40
  text "GND" at 6610.48,3895.1 h40
  text "CS" at 3538.48,3855.52 h40
  text "MOSI" at 6603.33,3855.52 h40
  text "RST" at 3817.35,3847.6 h50
  text "L" at 4937.31,3822 h60
  text "SCK" at 3525.48,3815.94 h40
  text "MISO" at 6603.33,3815.94 h40
  text "MISO" at 3518.33,3776.36 h40
  text "SCK" at 6610.48,3776.36 h40
  text "MOSI" at 3518.33,3736.78 h40
  text "CS" at 6623.48,3736.78 h40
  text "TFT" at 5919.03,3734.03 h50
  text "240x135" at 6032.88,3734.14 h60
  text "SPI1" at 6304.6,3734.06 h50
  text "GND" at 3525.48,3697.2 h40
  text "3.3" at 6617.38,3697.2 h40
  text "0" at 4715.15,3684.86 h40
  text "M0·BK" at 4849.94,3561.94 h50
  text "M1·BK" at 5203.27,3562.09 h50
  text "CAN" at 3829.09,3463.04 h50
  text "RS485" at 6249.4,3463.04 h50
  text "+" at 6159.4,3422.66 h40
  text "H" at 3789.4,3421.11 h40
  text "L" at 3959.9,3421.11 h40
  text "B" at 6190.4,3421.11 h40
  text "A" at 6431.4,3421.11 h40
  text "D" at 6462.4,3421.11 h40
  text "M4x4" at 3497.43,3396.9 h60
  text "SCREWS" at 3491.8,3345.48 h40
  text "MOTOR0" at 4179.19,3269.9 h80
  text "MOTOR1" at 5635.44,3269.89 h80
Bottom Silkscreen Layer:
  region: 4848.31,4422.08 4816.31,4422.08 4816.31,4438.08 4848.31,4438.08
  region: 5379.68,4422.08 5347.68,4422.08 5347.68,4438.08 5379.68,4438.08
  region: 6559.05,5294.31 6606.63,5298.24 6633.89,5325.5 6786.98,5325.5 6830.02,5355.5 6620.24,5355.5
  region: 6951.26,4902.09 6955.19,4949.67 6982.45,4976.93 6982.45,5130.02 7012.45,5173.07 7012.45,4963.28
  region: 3256.54,4902.09 3252.61,4949.67 3225.35,4976.93 3225.35,5130.02 3195.35,5173.07 3195.35,4963.28
  region: 3648.76,5294.31 3601.18,5298.24 3573.92,5325.5 3420.83,5325.5 3377.78,5355.5 3587.57,5355.5
  region: 3648.76,3174.39 3601.18,3170.46 3573.92,3143.2 3420.83,3143.2 3377.78,3113.2 3587.57,3113.2
  region: 3256.54,3566.6 3252.61,3519.02 3225.35,3491.76 3225.35,3338.68 3195.35,3295.63 3195.35,3505.41
  region: 6951.26,3566.61 6955.19,3519.03 6982.45,3491.77 6982.45,3338.68 7012.45,3295.63 7012.45,3505.42
  region: 6559.05,3174.39 6606.63,3170.46 6633.89,3143.2 6786.98,3143.2 6830.02,3113.2 6620.24,3113.2
  lines w8: 5103.9,5938.6 5103.9,6114.6 ; 4774.12,4399.5 ccw(c4794.12,4399.5) 4794.12,4379.5 4800.12,4385.5 5407.68,4385.5 5413.68,4379.5 ccw(c5413.68,4399.5) 5433.68,4399.5 5427.68,4405.5 5427.68,4478.11 5433.68,4484.11 ccw(c5413.68,4484.11) 5413.68,4504.11 5407.68,4498.11 4800.12,4498.11 4794.12,4504.11 ccw(c4794.12,4484.11) 4774.12,4484.11 4780.12,4478.11 4780.12,4405.5 4774.12,4399.5
  lines w10: 3674.37,3482.62 cw(c3689.37,3508.6) 3674.37,3534.58 ; 3813.43,3482.62 ccw(c3798.43,3508.6) 3813.43,3534.58 ; 4816.31,4421.68 4848.31,4421.68 4848.31,4438.11 ; 4816.31,4422.11 4816.31,4438.11 ; 5379.68,4421.68 5347.68,4421.68 5347.68,4438.11 ; 5379.68,4422.11 5379.68,4438.11 ; 6254.37,3456.81 cw(c6269.37,3482.79) 6254.37,3508.77 ; 6393.43,3456.81 ccw(c6378.43,3482.79) 6393.43,3508.77 ; 4816.31,4438.11 4848.31,4438.11 ; 4816.31,4438.11 4802.31,4438.11 4832.31,4468.11 4862.31,4438.11 4848.31,4438.11 ; 5347.68,4438.11 5379.68,4438.11 ; 5347.68,4438.11 5333.68,4438.11 5363.68,4468.11 5393.68,4438.11 5379.68,4438.11
  lines w12: 4582.72,5278.59 4648.31,5057.29 ; 5005.47,5057.42 5071.06,5278.72 ; 5133.9,5278.6 5199.49,5057.3 ; 5556.65,5057.42 5622.24,5278.72
  lines w16: 3202.77,3297.23 cw(c3332.25,3250.1) 3320.24,3387.37 ; 3202.77,5171.47 ccw(c3332.25,5218.6) 3320.24,5081.33 ; 3379.38,3120.61 ccw(c3332.25,3250.1) 3469.52,3238.09 ; 3379.38,5348.09 cw(c3332.25,5218.6) 3469.52,5230.61 ; 4979.01,6084.83 ccw(c5103.9,6026.6) 4998.34,5938.02 ; 5209.46,5938.02 ccw(c5103.9,6026.6) 5228.78,6084.83 ; 6738.28,3238.09 ccw(c6875.55,3250.1) 6828.42,3120.61 ; 6738.28,5230.61 cw(c6875.55,5218.6) 6828.42,5348.09 ; 6887.56,3387.37 cw(c6875.56,3250.1) 7005.04,3297.23 ; 6887.56,5081.33 ccw(c6875.56,5218.6) 7005.04,5171.47
  text "Motor_Ctrl" at 5314.13,4400.59 h80
  text "- DC" at 5996.77,4271.8 h35
  text "- RES" at 5996.77,4244.3 h35
  text "- CS" at 5996.77,4216.8 h35
  text "120" at 6354.9,3511.6 h40
  text "120" at 3774.9,3439.41 h40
